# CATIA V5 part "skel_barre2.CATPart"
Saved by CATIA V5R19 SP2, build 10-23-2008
Part number: skel_barre2
Bounding box of the stored display mesh (mm): x 2 to 22, y 19.19 to 31.173, z 0.952 to 10.42
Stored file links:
  E:\TRAVAIL\IAO\skel_barre2.CATPart
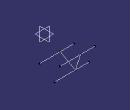
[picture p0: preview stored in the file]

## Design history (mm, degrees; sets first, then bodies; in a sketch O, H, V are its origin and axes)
Body1 (main body)
  Point1 "Point.A": stored without definition
  Point2 "Point.B": stored without definition
  Point3 "Point.Aprim": stored without definition
  Point4 "Point.Bprim": stored without definition
  Point5 "point_Asecond": stored without definition
  Point6 "point_Bsecond": stored without definition
  Point7 "point_Bsecond": stored without definition
  Point8 "point_Asecond": stored without definition
  Line1: type PtPt, FirstPoint Point7, SecondPoint Point8
  Point9 "Point.B": stored without definition
  Point10 "Point.M": stored without definition
  Point11 "Point.Bprim": stored without definition
  Point12 "Point.Mprim": stored without definition
  Point13 "point_Msecond": stored without definition
  Point14 "point_Bsecond": stored without definition
  Point15 "point_Msecond": stored without definition
  Point16 "point_Msecond": stored without definition
  Point17 "point_Bsecond": stored without definition
  Point18 "Point.Mprim": stored without definition
  Line2: type PtPt, FirstPoint Point18, SecondPoint Point17
  Plane1: stored without definition
  Point19 "Point.Aprim": stored without definition
  Line3 "axe_pivot_barre2_barre1": type Normal, RefPoint Point19, RefSkin Plane1, Start 0, End 20
  Line4 "axe_pivot_barre2_barre5": type Normal, RefPoint Point11, RefSkin Plane1, Start 0, End 20
  Line5 "axe_pivot_barre2_barre3": type Normal, RefPoint Point12, RefSkin Plane1, Start 0, End 20
  Point20 "Point.B": stored without definition
  Point21 "Point.C": stored without definition
  Plane2 "Plan_ref": stored without definition
  Point22 "Point.B": stored without definition
  Plane3 "Plan_ref": stored without definition
  Point23 "Point.C": stored without definition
